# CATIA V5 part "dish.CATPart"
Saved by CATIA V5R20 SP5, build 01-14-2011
Part number: dish
Material "Metal Green": density 7860 kg/m3, Young's modulus 2e+11 Pa, Poisson ratio 0.266
Bounding box of the stored display mesh (mm): x -134 to 134, y -133.803 to 133.803, z 0 to 15
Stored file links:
  E:\设计\180212313林恺昇\dish.CATPart
  C:\Program Files\Dassault Systemes\B20\intel_a\startup\materials\Catalog.CATMaterial
  C:\Program Files\Dassault Systemes\B20\intel_a\startup\materials\blue_env_512x512.jpg
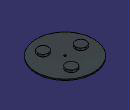
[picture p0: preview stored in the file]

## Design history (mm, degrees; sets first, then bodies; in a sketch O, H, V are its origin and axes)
Body1 (main body)
  Sketch1 on xy-plane, origin (0, 0, 0), H (1, 0, 0), V (0, 1, 0)
    circle A1 centre (0, 0) radius 134
    circle A2 centre (0, 0) radius 5
    point P1 (5, 0)
    radius A1 = 134
    radius A2 = 5
    coincidence: A2 P1, P1 H
  Pad1: profile Sketch1, direction (0, 0, 1), length 5
  Sketch2 on end face of Pad1, origin (0, 0, 5), H (1, 0, 0), V (0, 1, 0)
    circle A1 centre (0, 0) radius 75
    point P1 (38.6418, -64.2791)
    point P2 (-74.9883, -1.3252)
    point P3 (36.3465, 65.6044)
    radius A1 = 75
    distance P1 P2 = 129.9038
    distance P2 P3 = 129.9038 {= Sketch2.distance(P1 P2)}
    coincidence: A1 P1, A1 P2, A1 P3
  Circle1: type CtrRad, Start 0, End 180, Center Sketch2.P2, Support end face of Pad1, Radius 25, FirstDirection (1, 0, 0)
  Circle2: type CtrRad, Start 0, End 180, Center Sketch2.P3, Support end face of Pad1, Radius 25, FirstDirection (1, 0, 0)
  Circle3: type CtrRad, Start 0, End 180, Center Sketch2.P1, Support end face of Pad1, Radius 25, FirstDirection (1, 0, 0)
  Pad2: profile Circle1, length 10
  Pad3: profile Circle2, length 10
  Pad4: profile Circle3, length 10
Relations
  Sketch2.distance(P1 P2) = Sketch2.distance(P1 P2) (deactivated)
